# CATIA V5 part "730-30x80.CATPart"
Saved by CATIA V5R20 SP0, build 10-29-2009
Part number: 730-30x80
Definition: NONE
Nomenclature: 730-30x80
Source: Unknown
Description: 730-30x80
Bounding box of the stored display mesh (mm): x -19 to 19, y -18.312 to 18.312, z 0 to 80
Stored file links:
  C:\Users\Utente\Desktop\IO LAVORO\3D X SITO CF\X SITO\730\730-30x80.CATPart
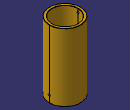
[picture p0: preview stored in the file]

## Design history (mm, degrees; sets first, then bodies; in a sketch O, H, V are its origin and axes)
Body1 "730-30x80" (main body)
  Solid1: solid without history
